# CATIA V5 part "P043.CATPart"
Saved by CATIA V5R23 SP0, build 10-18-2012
Part number: P043
Definition: Goupille elastique 8x80
Description: Goupille elastique ISO 8752 8x80
Bounding box of the stored display mesh (mm): x -80 to 0, y -4 to 3.985, z -3.996 to 3.996
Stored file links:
  C:\wamp\www\COURS\CONCEPTION GMP1\TITRE 02-SEMESTRE 2\03-TP7-PRESSE MECANIQUE\eleve\P043.CATPart
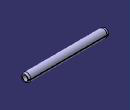
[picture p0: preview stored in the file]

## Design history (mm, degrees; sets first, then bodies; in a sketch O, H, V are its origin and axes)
Parameters
  Material = "St"
  d1_pin_nom_dia = 8 mm
  l_pin_length_nom = 80 mm
  d2_pin_id = 5.5 mm
  a_cham_max = 2 mm
  s_wall_th = 1.5 mm
  PartNumber = "Goupille elastique ISO 8752 8x80"
Set1
  Point1: (-40, 0, 0)
Body1 "PartBody" (main body)
  Sketch1 on zx-plane, origin (0, 0, 0), H (-1, 0, 0), V (0, 0, 1)
    point P1 (0, 3.4641)
    line L1 (0, 3.4641) -> (2, 4)
    point P2 (2, 4)
    point P3 (2, 4)
    line L2 (2, 4) -> (78, 4)
    point P4 (78, 4)
    line L3 (78, 4) -> (80, 3.4641)
    point P5 (80, 3.4641)
    point P6 (80, 3.4641)
    line L4 (80, 3.4641) -> (80, 2.5)
    line L5 (80, 2.5) -> (0, 2.5)
    line L6 (0, 2.5) -> (0, 3.4641)
    axis line L7 (-9.3888, 0) -> (37.524, 0)
    distance P1 L4 = 80 {= l_pin_length_nom}
    distance L5 L2 = 1.5 {= s_wall_th}
    angle L3 L2 = 15
    angle L1 L2 = 15
    distance L2 L7 = 4 {= d1_pin_nom_dia /2}
    distance V P2 = 2 {= a_cham_max}
    distance P4 P5 H = 2 {= a_cham_max}
    coincidence: P3 L1, P6 L3, P2 P3, P5 P6, P1 V
    horizontal: L2 H, L5 H, L7 H
    vertical: L4 V, L6 V
    fix: L7
  Shaft1: profile Sketch1, axis Sketch1.L7, angle 445, second angle -95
